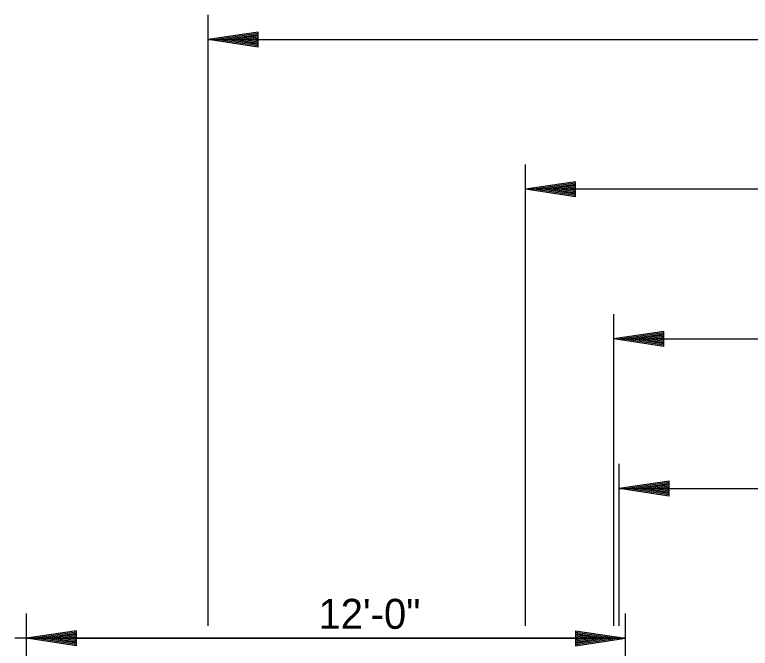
# Model space of a CAD drawing. Extents: x 138 to 3619, y -519 to 1449.
# Drawn here: x 378.9 to 526.3, y 603.4 to 730.4 of the extents above; entities that cross this region are included whole.
import ezdxf

# ---------------------------------------------------------------- set-up
doc = ezdxf.new("R2010")
doc.units = 0
doc.layers.add('R_Annotation', color=7, linetype='Continuous')
doc.layers.add('R_Dimension', color=7, linetype='Continuous')

msp = doc.modelspace()

# ---------------------------------------------------------------- linework, layer by layer
at = {"layer": 'R_Dimension'}
for p, q in [((417.63, 607.89), (417.63, 730.39)), ((427.63, 726.89), (417.63, 725.39)), ((427.63, 723.89), (427.63, 726.89)), ((417.63, 725.39), (804.9, 725.39)), ((427.63, 723.89), (417.63, 725.39)), ((427.63, 726.64), (419.3, 725.39)), ((427.63, 724.14), (419.3, 725.39)), ((427.63, 726.39), (421.02, 725.39)), ((427.63, 724.4), (421.02, 725.39)), ((427.63, 726.14), (422.68, 725.39)), ((427.63, 724.65), (422.68, 725.39)), ((427.63, 725.88), (424.38, 725.39)), ((427.63, 724.91), (424.38, 725.39)), ((427.63, 725.63), (426.05, 725.39)), ((427.63, 725.16), (426.05, 725.39)), ((481.25, 607.89), (481.25, 700.39)), ((491.25, 696.89), (481.25, 695.39)), ((491.25, 696.64), (482.92, 695.39)), ((491.25, 696.39), (484.64, 695.39)), ((491.25, 696.14), (486.3, 695.39)), ((491.25, 695.88), (488, 695.39)), ((491.25, 693.89), (491.25, 696.89)), ((491.25, 693.89), (481.25, 695.39)), ((741.28, 695.39), (481.25, 695.39)), ((491.25, 694.14), (482.92, 695.39)), ((491.25, 694.4), (484.64, 695.39)), ((491.25, 694.65), (486.3, 695.39)), ((491.25, 694.91), (488, 695.39)), ((491.25, 695.63), (489.67, 695.39)), ((491.25, 695.16), (489.67, 695.39)), ((498.95, 607.89), (498.95, 670.39)), ((508.95, 666.89), (498.95, 665.39)), ((508.95, 666.64), (500.62, 665.39)), ((508.95, 666.39), (502.34, 665.39)), ((508.95, 663.89), (508.95, 666.89)), ((508.95, 663.89), (498.95, 665.39)), ((500, 665.39), (722.53, 665.39)), ((508.95, 664.14), (500.62, 665.39)), ((508.95, 664.4), (502.34, 665.39)), ((508.95, 666.14), (504, 665.39)), ((508.95, 664.65), (504, 665.39)), ((508.95, 665.88), (505.7, 665.39)), ((508.95, 664.91), (505.7, 665.39)), ((508.95, 665.63), (507.37, 665.39)), ((508.95, 665.16), (507.37, 665.39)), ((500, 607.89), (500, 640.39)), ((510, 636.89), (500, 635.39)), ((510, 633.89), (510, 636.89)), ((500, 635.39), (722.53, 635.39)), ((510, 633.89), (500, 635.39)), ((510, 636.64), (501.67, 635.39)), ((510, 634.14), (501.67, 635.39)), ((510, 636.39), (503.39, 635.39)), ((510, 634.4), (503.39, 635.39)), ((510, 636.14), (505.06, 635.39)), ((510, 634.65), (505.06, 635.39)), ((510, 635.88), (506.75, 635.39)), ((510, 634.91), (506.75, 635.39)), ((510, 635.63), (508.42, 635.39)), ((510, 635.16), (508.42, 635.39)), ((381.26, 522.41), (381.26, 610.39)), ((501.26, 585.39), (501.26, 610.39)), ((391.26, 606.89), (381.26, 605.39)), ((391.26, 606.64), (382.93, 605.39)), ((391.26, 606.39), (384.65, 605.39)), ((391.26, 606.14), (386.32, 605.39)), ((391.26, 605.88), (388.01, 605.39)), ((391.26, 603.89), (391.26, 606.89)), ((491.26, 606.89), (501.26, 605.39)), ((491.26, 606.89), (491.26, 603.89)), ((491.26, 606.64), (499.59, 605.39)), ((491.26, 606.39), (497.87, 605.39)), ((491.26, 606.14), (496.21, 605.39)), ((491.26, 605.88), (494.51, 605.39)), ((501.26, 605.39), (378.87, 605.39)), ((381.26, 605.39), (501.26, 605.39)), ((391.26, 603.89), (381.26, 605.39)), ((391.26, 604.14), (382.93, 605.39)), ((391.26, 604.4), (384.65, 605.39)), ((391.26, 604.65), (386.32, 605.39)), ((391.26, 604.91), (388.01, 605.39)), ((391.26, 605.63), (389.68, 605.39)), ((391.26, 605.16), (389.68, 605.39)), ((491.26, 605.63), (492.84, 605.39)), ((491.26, 603.89), (501.26, 605.39)), ((491.26, 604.9), (494.51, 605.39)), ((491.26, 604.4), (497.87, 605.39)), ((491.26, 604.14), (499.59, 605.39)), ((491.26, 604.65), (496.21, 605.39)), ((491.26, 605.16), (492.84, 605.39))]:
    msp.add_line(p, q, dxfattribs=at)

# ---------------------------------------------------------------- texts
at = {"layer": 'R_Annotation'}
msp.add_text('12\'-0"', height=6, dxfattribs=at).set_placement((439.73, 607.3))

doc.saveas('drawing.dxf')
